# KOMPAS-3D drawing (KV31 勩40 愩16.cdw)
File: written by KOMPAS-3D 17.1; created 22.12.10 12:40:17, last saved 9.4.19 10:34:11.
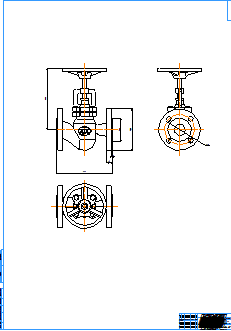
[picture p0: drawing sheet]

Title block, sheet 1: name: KV31 Ду40 Ру16; material: Внимание! Данный продукт является объектом авторского права ООО «Торговый Дом АДЛ». / Запрещается изменение, копирование, распространение / (в том числе путем копирования на другие сайты и ресурсы в Интернете) / или любое иное использование информации и объектов без предварительного / согласия правообладателя (ООО «Торговый Дом АДЛ»).; mass: 9; scale: 1:1; sheets: 1; organisation: ООО "Торговый дом АДЛ"; sheet format: A0; stored path: \\adlc.lan\data\АДЛ_ПКД\3D-модели\ADL production\Вентили ГРАНВЕНТ\KV31\KOMPAS 2D\KV31 Ду40.cdw

Views: Спереди 1, Проекционный вид 2, Вид 5
Dimensions and other numbers on the sheet: 84; 150; 2; 19; 200; 110; 220; 1:1; 1; 9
